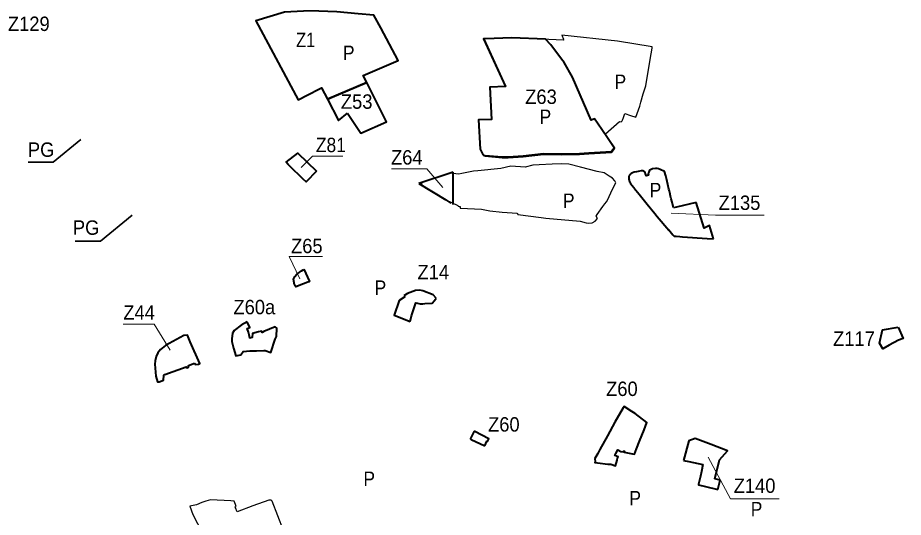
# Model space of a CAD drawing. Extents: x -650276 to -642489, y -1074311 to -1066658.
# Drawn here: x -647810 to -646336, y -1070699 to -1069867 of the extents above; entities that cross this region are included whole.
import ezdxf

# ---------------------------------------------------------------- set-up
doc = ezdxf.new("R2010")
doc.units = 0
doc.header["$LTSCALE"] = 9.6
for name, color, linetype, lineweight in [('2', 7, 'Continuous', 40), ('4', 7, 'Continuous', 40), ('42', 7, 'Continuous', 25), ('44', 7, 'Continuous', 40), ('45', 7, 'Continuous', 40), ('46', 7, 'Continuous', 13), ('59', 7, 'Continuous', 13), ('60', 7, 'Continuous', 35)]:
    doc.layers.add(name, color=color, linetype=linetype, lineweight=lineweight)

msp = doc.modelspace()

# ---------------------------------------------------------------- linework, layer by layer
at = {"layer": '4'}
for points in [[(-646748.31, -1070117.83), (-646753.45, -1070118.63), (-646755.74, -1070119.56), (-646757.76, -1070121.07), (-646759.06, -1070122.6), (-646759.78, -1070124), (-646760.32, -1070125.55), (-646760.5, -1070127.58), (-646760.22, -1070129.42), (-646762.07, -1070129.91), (-646763.9, -1070130.41), (-646763.98, -1070130.1), (-646764, -1070129.86), (-646764.94, -1070127.21), (-646765.19, -1070126.23), (-646765.51, -1070125.28), (-646765.97, -1070124.42), (-646767.38, -1070123), (-646768.25, -1070122.53), (-646769.17, -1070122.15), (-646770.43, -1070121.92), (-646772.19, -1070121.98), (-646777.37, -1070122.79), (-646780.28, -1070123.41), (-646784.13, -1070124.41), (-646787, -1070125.38), (-646788.77, -1070126.26), (-646789.61, -1070126.79), (-646791.03, -1070128.23)], [(-646718.8, -1070183.56), (-646721.09, -1070173.94), (-646722.4, -1070168.45), (-646723.4, -1070164.29), (-646724.86, -1070158.17), (-646725.39, -1070155.78), (-646726.17, -1070152.7), (-646728.14, -1070144.51), (-646730.45, -1070134.85), (-646731.54, -1070130.28), (-646733.35, -1070122.79), (-646740.92, -1070119.57), (-646743.33, -1070118.51), (-646745.78, -1070117.96), (-646748.31, -1070117.83)], [(-646791.03, -1070128.23), (-646791.64, -1070129), (-646792.11, -1070129.89), (-646792.76, -1070131.79), (-646792.97, -1070133.76), (-646792.84, -1070135.73), (-646792.42, -1070137.71), (-646792.18, -1070138.48), (-646791.84, -1070139.56), (-646791.13, -1070141.44), (-646790.86, -1070142.02), (-646790.29, -1070142.85), (-646784.8, -1070149.86), (-646784.45, -1070150.291)], [(-646784.45, -1070150.291), (-646784.18, -1070150.61), (-646783.937, -1070150.923), (-646775.93, -1070160.78), (-646762.52, -1070177.24)], [(-646762.52, -1070177.24), (-646749.79, -1070193.02), (-646745.61, -1070198.15), (-646726.48, -1070220.46), (-646726.36, -1070220.34), (-646719.7, -1070228.25), (-646717.71, -1070230.56)], [(-646680.68, -1070174.5), (-646713.74, -1070182.36), (-646718.8, -1070183.56)], [(-646651.86, -1070235.22), (-646656.96, -1070218.43), (-646658.64, -1070212.77), (-646667.64, -1070217.36), (-646680.61, -1070174.79), (-646680.68, -1070174.5)], [(-646717.71, -1070230.56), (-646714.42, -1070230.81), (-646708.2, -1070231.25), (-646703.67, -1070231.58), (-646662.41, -1070234.57), (-646651.86, -1070235.22)], [(-646655.95, -1070577.64), (-646682.29, -1070567.36), (-646692.98, -1070571.45), (-646701.87, -1070603.92)], [(-646649.71, -1070634.85), (-646642.32, -1070603.3), (-646628.69, -1070588.27), (-646655.95, -1070577.64)], [(-646701.87, -1070603.92), (-646693.18, -1070605.83), (-646669.59, -1070611.01)], [(-646669.59, -1070611.01), (-646672.13, -1070622.41), (-646673.91, -1070630.38), (-646676.414, -1070641.58)], [(-646645.03, -1070652.34), (-646641.09, -1070636.89), (-646649.71, -1070634.85)], [(-646676.414, -1070641.58), (-646676.81, -1070643.36), (-646677.13, -1070644.78), (-646665.42, -1070647.54), (-646645.03, -1070652.34)]]:
    msp.add_lwpolyline(points, dxfattribs=at)
at = {"layer": '42'}
for points in [[(-646901.388, -1069904.174), (-646987.56, -1069900.52), (-647032.16, -1069902.13), (-647033.853, -1069902.188)], [(-646753.995, -1069915.425), (-646811.935, -1069906.155), (-646904.446, -1069895.991), (-646901.388, -1069902.723), (-646902.06, -1069902.694), (-646901.388, -1069904.174)], [(-647033.853, -1069902.188), (-646998.06, -1069980.039), (-646998.716, -1069980.064)], [(-646831.912, -1070060.406), (-646808.49, -1070039.689), (-646805.65, -1070040.439), (-646803.87, -1070038.879), (-646803.43, -1070037.629), (-646801.84, -1070033.139), (-646799.45, -1070026.749), (-646790.27, -1070029.749), (-646781.39, -1070032.779), (-646774.86, -1070014.019), (-646772.96, -1070007.579), (-646768.91, -1069993.979), (-646764.81, -1069980.189), (-646757.45, -1069936.669), (-646754.36, -1069917.669), (-646753.995, -1069915.425)], [(-646998.716, -1069980.064), (-646998.06, -1069981.49), (-647023.975, -1069982.477)], [(-647023.975, -1069982.477), (-647021.27, -1070034.829), (-647021.345, -1070034.832)], [(-647021.345, -1070034.832), (-647021.27, -1070036.28), (-647043.157, -1070037.286)], [(-647043.157, -1070037.286), (-647040.12, -1070084.659), (-647036.03, -1070093.509), (-647034.17, -1070095.039), (-647031.73, -1070095.759), (-647003.49, -1070098.209), (-646993.92, -1070098.039), (-646968.89, -1070096.569), (-646934.63, -1070092.789), (-646904.97, -1070093.069)], [(-646904.97, -1070093.069), (-646874.9, -1070092.649), (-646859.29, -1070091.649), (-646821.89, -1070089.249), (-646817.427, -1070083.656), (-646831.912, -1070061.857), (-646831.305, -1070061.32), (-646831.912, -1070060.406)], [(-647367.67, -1070720.73), (-647377.04, -1070696.22), (-647386.39, -1070671.74), (-647388.31, -1070669.95), (-647391.74, -1070670.16), (-647418.28, -1070679.89), (-647444.78, -1070689.6), (-647447.31, -1070682.72), (-647447.76, -1070681.5), (-647446.22, -1070680.91), (-647447.58, -1070677.36), (-647449.69, -1070671.81), (-647455.17, -1070671.48), (-647489.21, -1070669.41), (-647496.64, -1070671.93), (-647503.3, -1070674.3), (-647512.51, -1070677.98), (-647523.27, -1070680.11), (-647518.19, -1070693.93), (-647502.59, -1070724.13)]]:
    msp.add_lwpolyline(points, dxfattribs=at)
msp.add_lwpolyline([(-646874.04, -1070205.5), (-646863.66, -1070208.37), (-646859.54, -1070209.09), (-646853.67, -1070208.44), (-646849.15, -1070205.9), (-646845.3, -1070201.3), (-646847.17, -1070197.38), (-646845.76, -1070194.67), (-646836.06, -1070181.31), (-646832.62, -1070177.08), (-646829.87, -1070173.61), (-646827.95, -1070169.52), (-646820.51, -1070153.68), (-646814.53, -1070141.96), (-646816.06, -1070138.5), (-646820.35, -1070134.43), (-646825.4, -1070130.78), (-646834.04, -1070125.34), (-646845.78, -1070122.84), (-646873.5, -1070115.8), (-646892.87, -1070110.82), (-646904.66, -1070110.24), (-646920.68, -1070110.58), (-646941.99, -1070111.74), (-646952.66, -1070112.57), (-646965.6, -1070115.74), (-646989.24, -1070114.17), (-646989.24, -1070114.17), (-647005.97, -1070117.89), (-647044.19, -1070121.78), (-647051.14, -1070122.49), (-647070.7, -1070126.64), (-647075.81, -1070127.72), (-647090.2, -1070125.64), (-647133.96, -1070140.44), (-647136.65, -1070141.75), (-647137.99, -1070143.09), (-647137.96, -1070144.66), (-647136.09, -1070146.97), (-647132.95, -1070149.08), (-647097.63, -1070170.37), (-647077.39, -1070179.57), (-647076.83, -1070180.73), (-647075.42, -1070181.53), (-647073.42, -1070181.47), (-647073.35, -1070184.01), (-647061.2, -1070184.6), (-647038.31, -1070185.73), (-647024.2, -1070188.68), (-647003.89, -1070190.89), (-646978.73, -1070192.54), (-646978.72, -1070193.6), (-646977.7, -1070193.62), (-646977.7, -1070194.45), (-646938.98, -1070199.89), (-646931.25, -1070200.56)], close=True, dxfattribs=at)
at = {"layer": '44'}
msp.add_lwpolyline([(-647312.485, -1070122.583), (-647329.932, -1070140.465), (-647334.81, -1070135.73), (-647357.4, -1070113.69), (-647359.8, -1070111.34), (-647362.87, -1070107.74), (-647343.454, -1070092.368)], close=True, dxfattribs=at)
at = {"layer": '44', "lineweight": 13}
msp.add_lwpolyline([(-647268.839, -1070097.432), (-647319.538, -1070097.432), (-647338.315, -1070116.223)], dxfattribs=at)
msp.add_lwpolyline([(-647268.839, -1070097.432), (-647319.538, -1070097.432), (-647338.315, -1070116.223)], dxfattribs=at)
at = {"layer": '45'}
for p, q in [((-647085.131, -1070123.926), (-647142.227, -1070143.236)), ((-647085.131, -1070123.926), (-647142.227, -1070143.236)), ((-647085.131, -1070177.975), (-647085.131, -1070123.926)), ((-647085.131, -1070177.975), (-647085.131, -1070123.926))]:
    msp.add_line(p, q, dxfattribs=at)
for points in [[(-647365.866, -1069857.774), (-647413.461, -1069872.442), (-647343.28, -1070003.81), (-647339.69, -1070001.95), (-647330.5, -1069997.19), (-647304.05, -1069983.79), (-647294.257, -1070002.745), (-647242.254, -1069980.33), (-647229.096, -1069974.658), (-647235, -1069963), (-647176.499, -1069938.333), (-647205.781, -1069883.796), (-647217.177, -1069862.57), (-647243.231, -1069860.34), (-647278.525, -1069857.002), (-647323.794, -1069855.468)], [(-647365.866, -1069857.774), (-647413.461, -1069872.442), (-647343.28, -1070003.81), (-647339.69, -1070001.95), (-647330.5, -1069997.19), (-647304.05, -1069983.79), (-647294.257, -1070002.745), (-647242.254, -1069980.33), (-647229.096, -1069974.658), (-647235, -1069963), (-647176.499, -1069938.333), (-647205.781, -1069883.796), (-647217.177, -1069862.57), (-647243.231, -1069860.34), (-647278.525, -1069857.002), (-647323.794, -1069855.468)], [(-647032.16, -1069902.13), (-647034.51, -1069902.21), (-646998.06, -1069981.49), (-647024.05, -1069982.48), (-647021.27, -1070036.28), (-647043.25, -1070037.29), (-647040.12, -1070086.11), (-647036.03, -1070094.96), (-647034.17, -1070096.49), (-647031.73, -1070097.21), (-647003.49, -1070099.66), (-646993.92, -1070099.49), (-646968.89, -1070098.02), (-646934.63, -1070094.24), (-646904.97, -1070094.52), (-646874.9, -1070094.1), (-646859.29, -1070093.1), (-646821.89, -1070090.7), (-646817.15, -1070084.76), (-646816.9, -1070084.45), (-646837.65, -1070053.22), (-646849.79, -1070035.17), (-646855.62, -1070037.66), (-646886.85, -1069966.26), (-646900.26, -1069941.64), (-646904.72, -1069935.84), (-646922.79, -1069912.31), (-646931.67, -1069902.89), (-646987.56, -1069900.52)], [(-647261.27, -1070026.12), (-647238.99, -1070059.05), (-647195.933, -1070040.107), (-647229.096, -1069974.658), (-647294.257, -1070002.745), (-647276, -1070038.08)], [(-647261.27, -1070026.12), (-647238.99, -1070059.05), (-647195.933, -1070040.107), (-647229.096, -1069974.658), (-647294.257, -1070002.745), (-647276, -1070038.08)], [(-647333.87, -1070285.66), (-647324.11, -1070306.21), (-647324.94, -1070306.63), (-647327.18, -1070307.52), (-647333.97, -1070310.22), (-647346.97, -1070315.05), (-647349, -1070312), (-647350.67, -1070302.55), (-647348.677, -1070297.894), (-647345.27, -1070293.99), (-647343.9, -1070292.96), (-647337.56, -1070288.43), (-647334.91, -1070286.51)], [(-647333.87, -1070285.66), (-647324.11, -1070306.21), (-647324.94, -1070306.63), (-647327.18, -1070307.52), (-647333.97, -1070310.22), (-647346.97, -1070315.05), (-647349, -1070312), (-647350.67, -1070302.55), (-647348.677, -1070297.894), (-647345.27, -1070293.99), (-647343.9, -1070292.96), (-647337.56, -1070288.43), (-647334.91, -1070286.51)], [(-647427.8, -1070373.32), (-647437.76, -1070378.66), (-647449.69, -1070387.83), (-647452.17, -1070392.38), (-647453.71, -1070401.81), (-647453.35, -1070406.09), (-647450.51, -1070416.96), (-647446.93, -1070429.99), (-647438.45, -1070428.47), (-647434.85, -1070422.64), (-647423.38, -1070421.87), (-647412.51, -1070421.5), (-647400.41, -1070421.08), (-647398.21, -1070421.15), (-647388.6, -1070424.24), (-647381.11, -1070402.45), (-647379.3, -1070397.57), (-647378.49, -1070383.91), (-647381.65, -1070381.45), (-647400.22, -1070389.64), (-647403.27, -1070390.91), (-647404, -1070388.84), (-647409.36, -1070390.24), (-647419.08, -1070392.52), (-647419.68, -1070399.59), (-647423.58, -1070400.59), (-647424.54, -1070394.78), (-647425.99, -1070390.47), (-647427.96, -1070384.64), (-647423.57, -1070382.64)], [(-647427.8, -1070373.32), (-647437.76, -1070378.66), (-647449.69, -1070387.83), (-647452.17, -1070392.38), (-647453.71, -1070401.81), (-647453.35, -1070406.09), (-647450.51, -1070416.96), (-647446.93, -1070429.99), (-647438.45, -1070428.47), (-647434.85, -1070422.64), (-647423.38, -1070421.87), (-647412.51, -1070421.5), (-647400.41, -1070421.08), (-647398.21, -1070421.15), (-647388.6, -1070424.24), (-647381.11, -1070402.45), (-647379.3, -1070397.57), (-647378.49, -1070383.91), (-647381.65, -1070381.45), (-647400.22, -1070389.64), (-647403.27, -1070390.91), (-647404, -1070388.84), (-647409.36, -1070390.24), (-647419.08, -1070392.52), (-647419.68, -1070399.59), (-647423.58, -1070400.59), (-647424.54, -1070394.78), (-647425.99, -1070390.47), (-647427.96, -1070384.64), (-647423.57, -1070382.64)], [(-646344.93, -1070382.33), (-646336.25, -1070400.875), (-646344.26, -1070403.84), (-646359.769, -1070412.361), (-646370.56, -1070418.29), (-646375.63, -1070408.76), (-646370.624, -1070386.792)], [(-647515.73, -1070442.32), (-647514.23, -1070444.18), (-647509.22, -1070443.62), (-647506.95, -1070442.71), (-647522.54, -1070406.51), (-647527.1, -1070395.72), (-647533.1, -1070396.26), (-647564.01, -1070412.59), (-647572.37, -1070419.41), (-647576.48, -1070425.09), (-647579.22, -1070431.05), (-647581.04, -1070438.4), (-647581.54, -1070443.7), (-647580.1, -1070463.69), (-647576.92, -1070473), (-647574.28, -1070473.46), (-647567.32, -1070470.66), (-647566.55, -1070462.22), (-647565.11, -1070461.12), (-647529.74, -1070448.27), (-647528.28, -1070449.87), (-647525.54, -1070448.89), (-647525.45, -1070446.21)], [(-647515.73, -1070442.32), (-647514.23, -1070444.18), (-647509.22, -1070443.62), (-647506.95, -1070442.71), (-647522.54, -1070406.51), (-647527.1, -1070395.72), (-647533.1, -1070396.26), (-647564.01, -1070412.59), (-647572.37, -1070419.41), (-647576.48, -1070425.09), (-647579.22, -1070431.05), (-647581.04, -1070438.4), (-647581.54, -1070443.7), (-647580.1, -1070463.69), (-647576.92, -1070473), (-647574.28, -1070473.46), (-647567.32, -1070470.66), (-647566.55, -1070462.22), (-647565.11, -1070461.12), (-647529.74, -1070448.27), (-647528.28, -1070449.87), (-647525.54, -1070448.89), (-647525.45, -1070446.21)], [(-646802.19, -1070516.26), (-646816.42, -1070540.49), (-646828.45, -1070562.89), (-646841.16, -1070585.79), (-646844.76, -1070592.54), (-646849.72, -1070600.98), (-646848.99, -1070606.28), (-646849.59, -1070607.4), (-646844.96, -1070607.98), (-646827.88, -1070610.12), (-646822.99, -1070610.51), (-646815.05, -1070613.14), (-646812.5, -1070603.78), (-646811.5, -1070600.29), (-646810.82, -1070598.23), (-646816.11, -1070595.8), (-646814.52, -1070592.78), (-646811.06, -1070586.67), (-646806.41, -1070589), (-646802.06, -1070589.93), (-646801.73, -1070588.37), (-646800.13, -1070588.71), (-646800.47, -1070590.28), (-646784.18, -1070593.76), (-646784, -1070593.34), (-646783.59, -1070593.52), (-646779.9, -1070584.92), (-646774.91, -1070571.88), (-646771.17, -1070562.7), (-646767.63, -1070553.09), (-646762.71, -1070540.85), (-646782.63, -1070526.02), (-646788, -1070522.49), (-646800.94, -1070514.04)], [(-646802.19, -1070516.26), (-646816.42, -1070540.49), (-646828.45, -1070562.89), (-646841.16, -1070585.79), (-646844.76, -1070592.54), (-646849.72, -1070600.98), (-646848.99, -1070606.28), (-646849.59, -1070607.4), (-646844.96, -1070607.98), (-646827.88, -1070610.12), (-646822.99, -1070610.51), (-646815.05, -1070613.14), (-646812.5, -1070603.78), (-646811.5, -1070600.29), (-646810.82, -1070598.23), (-646816.11, -1070595.8), (-646814.52, -1070592.78), (-646811.06, -1070586.67), (-646806.41, -1070589), (-646802.06, -1070589.93), (-646801.73, -1070588.37), (-646800.13, -1070588.71), (-646800.47, -1070590.28), (-646784.18, -1070593.76), (-646784, -1070593.34), (-646783.59, -1070593.52), (-646779.9, -1070584.92), (-646774.91, -1070571.88), (-646771.17, -1070562.7), (-646767.63, -1070553.09), (-646762.71, -1070540.85), (-646782.63, -1070526.02), (-646788, -1070522.49), (-646800.94, -1070514.04)], [(-647032.738, -1070579.83), (-647029.168, -1070572.13), (-647028.248, -1070572.63), (-647025.868, -1070568.26), (-647049.248, -1070555.64), (-647050.098, -1070555.74), (-647050.868, -1070556.59), (-647052.498, -1070559.7), (-647056.518, -1070567.41), (-647056.528, -1070568.32), (-647055.518, -1070569.07)]]:
    msp.add_lwpolyline(points, close=True, dxfattribs=at)
for points in [[(-647142.227, -1070143.236), (-647097.63, -1070170.37), (-647088.916, -1070175.672)], [(-647142.227, -1070143.236), (-647097.63, -1070170.37), (-647088.916, -1070175.672)], [(-647113.37, -1070333.96), (-647118.28, -1070328.29), (-647135.94, -1070321.54), (-647140.83, -1070320.47), (-647147.66, -1070321.04), (-647161.17, -1070326.29), (-647167.03, -1070329.81)], [(-647167.03, -1070329.81), (-647165.36, -1070331.59), (-647174.81, -1070338.01), (-647183.55, -1070362.35), (-647156.9, -1070372.69)], [(-647156.9, -1070372.69), (-647154.31, -1070363.46), (-647151.09, -1070353.15), (-647147.6, -1070341.95), (-647144.57, -1070342.42), (-647139.84, -1070343.16), (-647135.62, -1070343.32), (-647132.49, -1070342.91)], [(-647132.49, -1070342.91), (-647119.88, -1070342.1), (-647116.03, -1070337.68), (-647113.37, -1070333.96)]]:
    msp.add_lwpolyline(points, dxfattribs=at)
at = {"layer": '46'}
for points in [[(-647187.627, -1070118.571), (-647128.949, -1070118.571), (-647102.191, -1070149.577)], [(-647187.627, -1070118.571), (-647128.949, -1070118.571), (-647102.191, -1070149.577)], [(-647302.639, -1070264.673), (-647358.031, -1070264.673), (-647340.193, -1070301.786)], [(-647302.639, -1070264.673), (-647358.031, -1070264.673), (-647340.193, -1070301.786)], [(-647634.056, -1070376.951), (-647582.888, -1070376.951), (-647556.111, -1070420.553)], [(-647634.056, -1070376.951), (-647582.888, -1070376.951), (-647556.111, -1070420.553)]]:
    msp.add_lwpolyline(points, dxfattribs=at)
at = {"layer": '59'}
for points in [[(-646567.835, -1070195.719), (-646648.755, -1070195.719), (-646722.263, -1070192.418)], [(-646542.723, -1070668.026), (-646623.643, -1070668.026), (-646660.881, -1070598.727)]]:
    msp.add_lwpolyline(points, dxfattribs=at)
at = {"layer": '60'}
for points in [[(-647792.254, -1070107.298), (-647750.945, -1070107.298), (-647704.94, -1070069.715)], [(-647792.254, -1070107.298), (-647750.945, -1070107.298), (-647704.94, -1070069.715)], [(-647714.329, -1070238.836), (-647672.08, -1070238.836), (-647619.504, -1070195.616)], [(-647714.329, -1070238.836), (-647672.08, -1070238.836), (-647619.504, -1070195.616)]]:
    msp.add_lwpolyline(points, dxfattribs=at)

# ---------------------------------------------------------------- texts
at = {"layer": '2', "width": 0.95}
msp.add_text('Z129', height=24, dxfattribs=at).set_placement((-647826.051, -1069889.189))
at = {"layer": '44', "width": 0.9}
msp.add_text('Z81', height=24, dxfattribs=at).set_placement((-647313.531, -1070090.851))
msp.add_text('Z81', height=24, dxfattribs=at).set_placement((-647313.531, -1070090.851))
at = {"layer": '46'}
for s, width, p in [('Z1', 0.85, (-647346.649, -1069916.072)), ('Z1', 0.85, (-647346.649, -1069916.072)), ('Z63', 0.95, (-646965.327, -1070010.57)), ('Z53', 0.95, (-647272.017, -1070018.639)), ('Z53', 0.95, (-647272.017, -1070018.639)), ('Z64', 0.95, (-647188.663, -1070111.521)), ('Z64', 0.95, (-647188.663, -1070111.521)), ('Z65', 0.95, (-647355.018, -1070259.014)), ('Z65', 0.95, (-647355.018, -1070259.014)), ('Z14', 0.95, (-647144.477, -1070302.522)), ('Z60a', 0.95, (-647450.804, -1070360.702)), ('Z44', 0.95, (-647634.087, -1070369.724)), ('Z44', 0.95, (-647634.087, -1070369.724)), ('Z117', 0.95, (-646453.122, -1070413.348)), ('Z60', 0.95, (-646830.725, -1070496.795)), ('Z60', 0.95, (-647027.184, -1070556.06))]:
    msp.add_text(s, height=24, dxfattribs=dict(at, width=width)).set_placement(p)
at = {"layer": '59', "width": 0.95}
for s, p in [('Z135', (-646643.568, -1070187.052)), ('Z140', (-646618.457, -1070658.164))]:
    msp.add_text(s, height=24, dxfattribs=at).set_placement(p)
at = {"layer": '60'}
for s, width, p in [('P', 0.9, (-647268.59, -1069937.47)), ('P', 0.9, (-647268.59, -1069937.47)), ('P', 0.9, (-646816.629, -1069985.717)), ('P', 0.9, (-646816.629, -1069985.717)), ('P', 0.9, (-646941.403, -1070043.945)), ('P', 0.9, (-646941.403, -1070043.945)), ('PG', 0.95, (-647792.805, -1070098.685)), ('PG', 0.95, (-647792.805, -1070098.685)), ('P', 0.9, (-646758.187, -1070165.956)), ('P', 0.9, (-646902.585, -1070183.692)), ('P', 0.9, (-646902.585, -1070183.692)), ('PG', 0.95, (-647717.94, -1070228.451)), ('PG', 0.95, (-647717.94, -1070228.451)), ('P', 0.9, (-647215.907, -1070328.431)), ('P', 0.9, (-647215.907, -1070328.431)), ('P', 0.9, (-647234.488, -1070646.552)), ('P', 0.9, (-646791.982, -1070678.937)), ('P', 0.9, (-646791.982, -1070678.937)), ('P', 0.9, (-646590.032, -1070697.137))]:
    msp.add_text(s, height=24, dxfattribs=dict(at, width=width)).set_placement(p)

doc.saveas('drawing.dxf')
